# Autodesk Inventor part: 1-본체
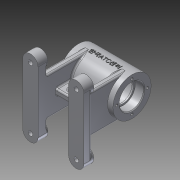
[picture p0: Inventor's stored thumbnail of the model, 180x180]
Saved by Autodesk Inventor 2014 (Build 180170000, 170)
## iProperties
Created: 2015-11
Part Number: 1-본체
Material: 알루미늄 6061
Document SubType Name: Modeling
Designer: test_25
Density: 2.71 g/cm^3
Appearance: 알루미늄 - 평지
Mass: 356.924 g
Surface Area: 463.355 cm^2
Volume: 131.706 cm^3
Author: test_25
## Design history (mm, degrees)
sketch "스케치1"
  geometry: L1 (-35, 16)-(-23, 16); L2 (-23, 16)-(-23, 14); L3 (-23, 14)-(-21, 14); L4 (-21, 14)-(-21, 21); L5 (-21, 21)-(21, 21); L6 (21, 21)-(21, 14); L7 (21, 14)-(23, 14); L8 (23, 14)-(23, 16); L9 (23, 16)-(35, 16); L10 (35, 16)-(35, 25); L11 (35, 25)-(-35, 25); L12 (-35, 25)-(-35, 16); L13 (-35, 0)-(35, 0); 1 further point
  constraints: 26 end point, 9 parallel, 2 perpendicular, 1 collinear, 1 horizontal, 1 midpoint, 1 vertical alignment
  dimensions: "d0" = 70 distance between parallel lines of L10 L12; "d1" = 28 diameter of L3 L13; "d2" = 28 diameter of L7 L13; "d3" = 32 diameter of L1 L13; "d4" = 32 diameter of L9 L13; "d5" = 42 diameter of L5 L13; "d6" = 12 distance of L1.start L1.end; "d7" = 12 distance of L8.end L9.end; "d9" = 50 diameter of L11 L13; "d11" = 70 distance of L13.start L13.end; "d12" = 35 distance of point (0, 0) L13.start; "d14" = 42 distance of L4.end L5.end; "d15" = 2 distance of L2.end L3.end
revolve "회전1" sketch "스케치1" stored, may be unused: angle "d16" = 90 deg
node "작업 평면1"
sketch "스케치3"
  geometry: L1 (-40, 50)-(-20, 50); L2 (-20, 50)-(-20, -50); L3 (-20, -50)-(-40, -50); L4 (-40, -50)-(-40, 50); L5 (-40, 50)-(-20, -50); L6 (-20, 50)-(-40, -50); L7 (20, 50)-(40, 50); L8 (40, 50)-(40, -50); L9 (40, -50)-(20, -50); L10 (20, -50)-(20, 50); L11 (20, 50)-(40, -50); L12 (40, 50)-(20, -50); 7 further points
  constraints: 24 end point, 7 midpoint, 4 parallel, 2 horizontal, 2 horizontal alignment, 2 perpendicular, 1 vertical alignment
  dimensions: "d32" = 100 distance of L7.end L8.end; "d33" = 100 distance of L3.end L1.start; "d34" = 40 distance from line of L4 point (0, 0); "d35" = 40 distance from line of L8 point (0, 0); "d36" = 20 distance of L7.start L7.end; "d37" = 20 distance of L1.start L1.end
extrude "돌출2" join sketch "스케치3" distance "d28" = 10; taper "d29" = 0 deg
sketch "스케치5"
  geometry: L1 (-20, 50)-(-20, -50) reference; L2 (-28, -25)-(-20, -25); L3 (-20, -25)-(-20, 25); L4 (-20, 25)-(-28, 25); L5 (-28, 25)-(-28, -25); L6 (-28, -25)-(-20, 25); L7 (-20, -25)-(-28, 25); 3 further points
  constraints: 12 end point, 3 midpoint, 2 parallel, 1 horizontal, 1 horizontal alignment, 1 perpendicular, 1 point on line
  dimensions: "d38" = 8 distance of L2.start L2.end; "d39" = 50 distance of L4.end L2.start
extrude "돌출3" join sketch "스케치5" stored distance "d40" = 10; taper "d41" = 0 deg
fillet "모깎기1" dims "d42" = 10
fillet "모깎기2" dims "d43" = 10
sketch "스케치7"
  geometry: C1 r 10 at (30, 40); A1 r 10 centre (30, 40) between (40, 40) and (20, 40) reference; 1 further point
  constraints: 1 centre point, 1 coincident
  dimensions: "d44" = 20 diameter of C1
extrude "돌출4" join sketch "스케치7" distance "d45" = 3; taper "d46" = 0 deg
sketch "스케치8"
  geometry: C1 r 10 at (0, 0) reference; 3 further points
  constraints: 2 coincident
hole "구멍1" sketch "스케치8" at (0, 0) diameter "d47" = 6; stored, may be unused: countersink angle "d51" = 90 deg, drill point angle "d53" = 118 deg; dims "d48" = 6, "d49" = 12, "d50" = 4, "d52" = 8
node "작업 평면3"
sketch "스케치9"
  geometry: C1 r 5 at (0, 0); 1 further point
  constraints: 1 centre point, 1 coincident
  dimensions: "d58" = 10 diameter of C1
extrude "돌출5" join sketch "스케치9" stored distance "d59" = 3; taper "d60" = 0 deg
sketch "스케치10"
  geometry: C1 r 5 at (0, 0) reference; 1 further point
  constraints: 1 coincident
hole "구멍2" sketch "스케치10" at (0, 0) diameter "d61" = 5.188; stored, may be unused: countersink angle "d65" = 90 deg, drill point angle "d67" = 118 deg; dims "d62" = 10, "d63" = 12, "d64" = 4, "d66" = 20
sketch "스케치11" dims "d68" = 40
  geometry: C1 r 25 at (0, 0) reference; C2 r 16 at (0, 0) reference; 2 further points
  constraints: 2 vertical alignment, 1 coincident, 2 other
hole "구멍3" sketch "스케치11" at (0, 20) diameter "d69" = 3.242; stored, may be unused: countersink angle "d73" = 90 deg, drill point angle "d75" = 118 deg; dims "d70" = 8, "d71" = 12, "d72" = 4, "d74" = 10
sketch "스케치12"
  geometry: L1 (-20, -58)-(-20, 0) reference; L2 (20, -58)-(20, 0) reference; L3 (-20, -45)-(20, -45); L4 (-35, -25)-(35, -25) reference; 1 further point
  constraints: 2 end point, 2 point on line, 1 perpendicular
  dimensions: "d79" = 20 distance between parallel lines of L3 L4
feature "리브1" sketch "스케치12" dims "d80" = 1, "d81" = 8, "d82" = 0, "d83" = 0, "d84" = 1, "d85" = 1
sketch "스케치13"
  geometry: L1 (0, 0)-(40, 0) reference; L2 (12, -10.322)-(28, -10.322); L3 (12, -6.822)-(28, -6.822); L4 (28, -13.822)-(12, -13.822); L5 (60, -43.322)-(40, -43.322) reference; A1 r 3.5 centre (12, -10.322) between (12, -6.822) and (12, -13.822); A2 r 3.5 centre (28, -10.322) between (28, -13.822) and (28, -6.822); 3 further points
  constraints: 8 end point, 5 point on circle, 4 tangent, 2 centre point, 2 parallel, 1 midpoint, 1 vertical alignment
  dimensions: "d86" = 33 distance from line of L5 point (20, -10.322); "d87" = 23 dimension on A2 A1; "d88" = 3.5 radius of A2
extrude "돌출6" cut sketch "스케치13" stored distance "d89" = 3; taper "d90" = 0 deg
chamfer "모따기1" distance "d91" = 1; stored, may be unused: second distance "d92" = 2, angle "d93" = 45 deg
fillet "모깎기3" dims "d94" = 0.3
fillet "모깎기4" dims "d95" = 2
fillet "모깎기5" dims "d96" = 2
fillet "모깎기6" dims "d97" = 2
fillet "모깎기7" dims "d98" = 2
fillet "모깎기8" dims "d99" = 2
fillet "모깎기9" dims "d100" = 2
node "작업 평면5"
sketch "스케치14"
  geometry: L1 (-35, -25)-(-35, 25) reference; L2 (-35, 25)-(35, 25) reference; 2 further points
  constraints: 1 other
  dimensions: "d102" = 35 distance from line of point (0, 0) L1; "d103" = 25 distance from line of L2 point (0, 0)
feature "엠보싱1" sketch "스케치14" dims "d0" = 70, "d1" = 28, "d2" = 28, "d3" = 32, "d4" = 32, "d5" = 42, "d6" = 12, "d7" = 12, "d9" = 50, "d11" = 70, "d12" = 35, "d14" = 42, "d15" = 2, "d28" = 10, "d29" = 0, "d104" = 0.5, "d105" = 0
fillet "모깎기10" dims "d106" = 2
fillet "모깎기11" dims "d107" = 3
fillet "모깎기12" dims "d108" = 3
node "솔리드1"
mirror "대칭1"
pattern_linear "직사각형 패턴1"
mirror "대칭2"
pattern_circular "원형 패턴1" dims angle "d77" = 360 deg
mirror "대칭3"
other parameters: "d17" = -68, "d57" = -96
